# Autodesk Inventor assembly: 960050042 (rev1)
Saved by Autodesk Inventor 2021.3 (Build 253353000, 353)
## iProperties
Created: 2023-03
Part Number: 960050042 (rev1)
Document SubType Name: Assembly
Designer: AdminForWorker
Title: 960050042 (rev1) v2
Author: AdminForWorker
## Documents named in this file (2)
- z:\worker\convert-fusion-r08-cosv3\tmp\job-1\3553\output\files\82b4d9ad-b575-4129-b9ca-4964d6b72adf\960050042 (rev1) v2_3.iam
- z:\worker\convert-fusion-r08-cosv3\tmp\job-1\3553\output\files\82b4d9ad-b575-4129-b9ca-4964d6b72adf\960050042 (rev1).ipt
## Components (1 placed, 1 different names)
1. 960050042 (rev1):1
